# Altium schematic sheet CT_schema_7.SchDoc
size 296 x 198 mm
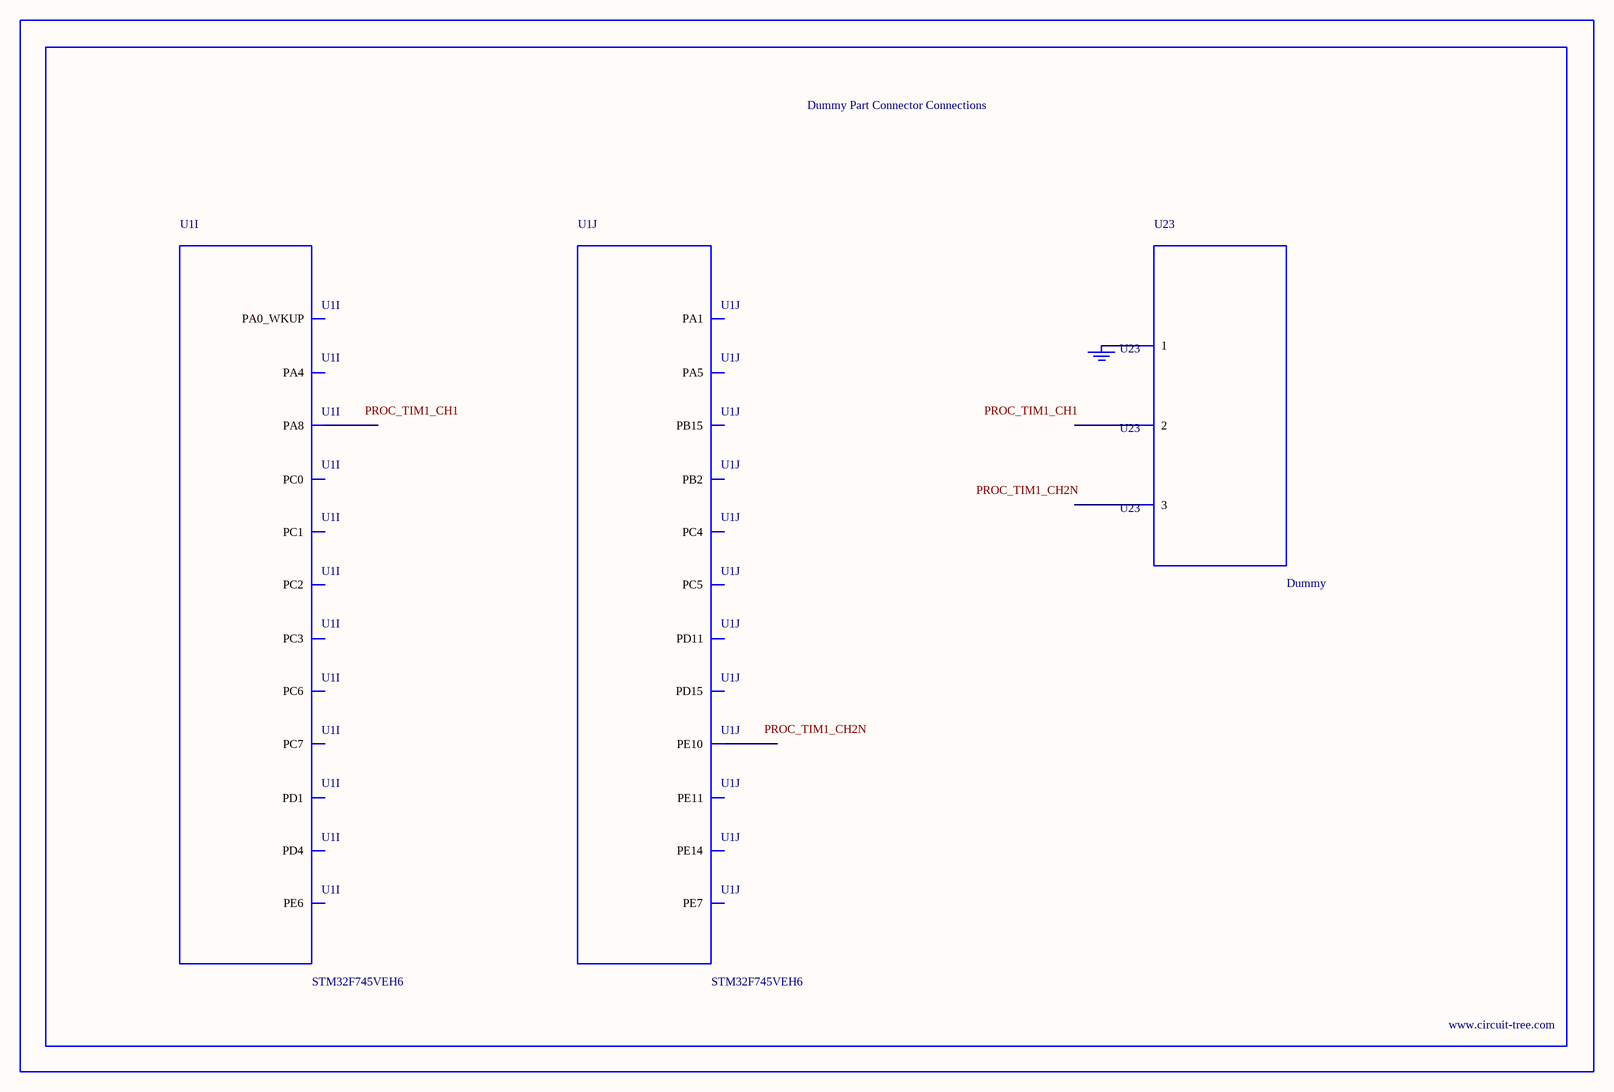
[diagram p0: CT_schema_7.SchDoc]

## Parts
BORDER6  (no value)
GND_INSTANCE_6_0  (no value)
U1  STM32F745VEH6  [TFBGA100]  (parts I,J of 10)
U23  Dummy  [DUMMY_PACKAGE_257]

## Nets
NetGND_INSTANCE_6_0_0: GND_INSTANCE_6_0.0(GND) U23.1

Not connected (* = marked no-connect by the designer): U1 D7(PD4) D9(PA8) E2(PC2) E3(PE6) E8(PD1) E10(PC7) F1(PC0) F2(PC1) F3(PC3) F10(PC6) G2(PA0_WKUP) G3(PA4) G4(PC4) G5(PB2) G6(PE10) G7(PE14) G8(PD15) G9(PD11) G10(PB15) H2(PA1) H3(PA5) H4(PC5) H5(PE7) H6(PE11); U23 2 3

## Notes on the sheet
- Labels drawn without touching a wire or pin: PROC_TIM1_CH1, PROC_TIM1_CH2N

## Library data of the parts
BORDER6 = BORDER_PAGE6
GND_INSTANCE_6_0 = GND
